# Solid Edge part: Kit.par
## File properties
Sűrűség: 0,000 kg/m^3
Pontosság: 0,990
Author: ahadarics
Last saved by: psaghy
Revision: 77
Username: ahadarics
Dokumentum tartalom típus: 0
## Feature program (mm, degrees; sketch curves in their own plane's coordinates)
base feature "unnamed BaseFeature 1"
sketch for "Furat_1" plane through (0, 0, 48) normal (0, 0, 1) x-axis (0.707107, -0.707107, 0)
  hole centre (0, 50.9117) bore radius 4.188
hole "Furat_1" nominal diameter 10 finite  VBottomAngle = 118 deg; ThreadDepth = 17 mm
sketch for "unnamed Hole 1" plane through (0, 0, 48) normal (0, 0, 1) x-axis (0.707107, -0.707107, 0)
  hole centre (-50.9117, 0) bore radius 4.188
hole "unnamed Hole 1" finite
sketch for "unnamed Hole 2" plane through (0, 0, 48) normal (0, 0, 1) x-axis (0.707107, -0.707107, 0)
  hole centre (0, -50.9117) bore radius 4.188
hole "unnamed Hole 2" finite
sketch for "unnamed Hole 3" plane through (0, 0, 48) normal (0, 0, 1) x-axis (0.707107, -0.707107, 0)
  hole centre (50.9117, 0) bore radius 4.188
hole "unnamed Hole 3" finite
pattern "unnamed Pattern 1" of "Furat_1", "unnamed Hole 1", "unnamed Hole 2", "unnamed Hole 3"
sketch for "Furat_5" plane through (46.5, -0.0074, 25.7488) normal (1, 0, 0) x-axis (0, 0, -1)
hole "Furat_5" diameter 16.662 finite  ThreadDepth = 17 mm
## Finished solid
Body 1: solid body, 572 faces, 1311 edges, 806 vertices, 7 internal voids.
  Faces by surface: cylinder 205, plane 152, cone 70, torus 54, sphere 53, spline 26, swept 12
  Edges by curve: curve on surface 497, circle 445, line 343, spline 26
Bounding box of the edges (mm; curved faces can reach further): 93.000 x 93.000 x 72.000, from (-46.5, -46.5, 8) to (46.5001, 46.5, 80).
Cylindrical faces by radius (mm): R0.3812 x2, R0.3829 x1, R0.3841 x2, R0.3867 x2, R0.3906 x1, R0.3923 x2, R0.4494 x1, R0.4682 x1, R0.4781 x1, R0.4828 x4, R0.4915 x2, R0.4958 x2, R0.5079 x2, R0.5081 x2, R0.5091 x1, R0.5418 x1, R0.5784 x1, R0.6016 x2, R0.6314 x2, R0.6541 x2, R0.6656 x2, R0.6796 x1, R0.6854 x1, R0.7231 x1, R0.756 x1, R0.7598 x2, R0.7606 x2, R0.7952 x1, R0.7968 x1, R0.8489 x1, R0.8923 x1, R0.9223 x1, R1 x43, R1.0009 x1, R1.0016 x19, R1.0018 x24, R1.01 x1, R1.0286 x1, R1.1393 x1, R1.2532 x1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
Conical faces (half-angle, radius in mm at the cone's reference point): 0.0028 deg R1.0012 x2, 0.0036 deg R1.0008 x6, 1 deg R23.75 x6, 1 deg R35 x6, 1.6538 deg R14.25 x1, 3.5477 deg R15.2454 x1, 5.1705 deg R12.9 x1, 8.3742 deg R12.5032 x1, 13.2989 deg R13.6846 x1, 14.7738 deg R13.2787 x1, 15 deg R21.1406 x1, 25.0169 deg R16.81 x1, 30 deg R6.1443 x1, 30 deg R14.8557 x2, 30 deg R15.1443 x1, 30 deg R22.125 x1, 38.6598 deg R31.7888 x6, 38.6598 deg R38.5 x1, 41.1859 deg R39.25 x3, 45 deg R3.75 x1, 45 deg R3.875 x1, 45 deg R5.3 x8, 45 deg R7.85 x8, 45 deg R8.67 x1, 45 deg R12.65 x2, 45 deg R17.85 x1, 59 deg R3.25 x1, 59 deg R4.188 x4
Toroidal faces (ring radius, tube radius in mm): R5.3 r0.3 x4, R5.7 r0.3 x1, R7.95 r0.2 x4, R8.65 r0.5 x4, R11.5 r1 x3, R12.8 r0.3 x1, R12.8088 r0.3 x1, R13.9279 r0.25 x1, R14.7464 r0.5 x1, R17.3 r0.2 x1, R19.75 r2 x1, R20.1163 r0.5 x1, R22.75 r1 x1, R23 r0.5 x1, R24.7327 r1 x6, R28.0969 r1 x6, R34.0061 r1 x6, R43 r1 x3, R46.9806 r1 x2, R47 r1 x6
Spherical faces by radius (mm): R1 x53
Planar faces by outward normal: +x 22, +y 8, +z 31, -x 1, -y 8, -z 23, oblique 59
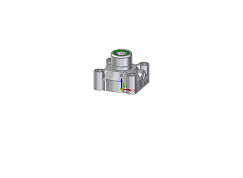
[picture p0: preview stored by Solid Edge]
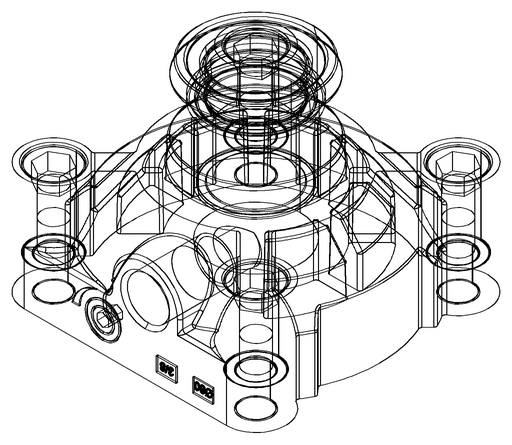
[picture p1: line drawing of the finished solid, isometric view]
